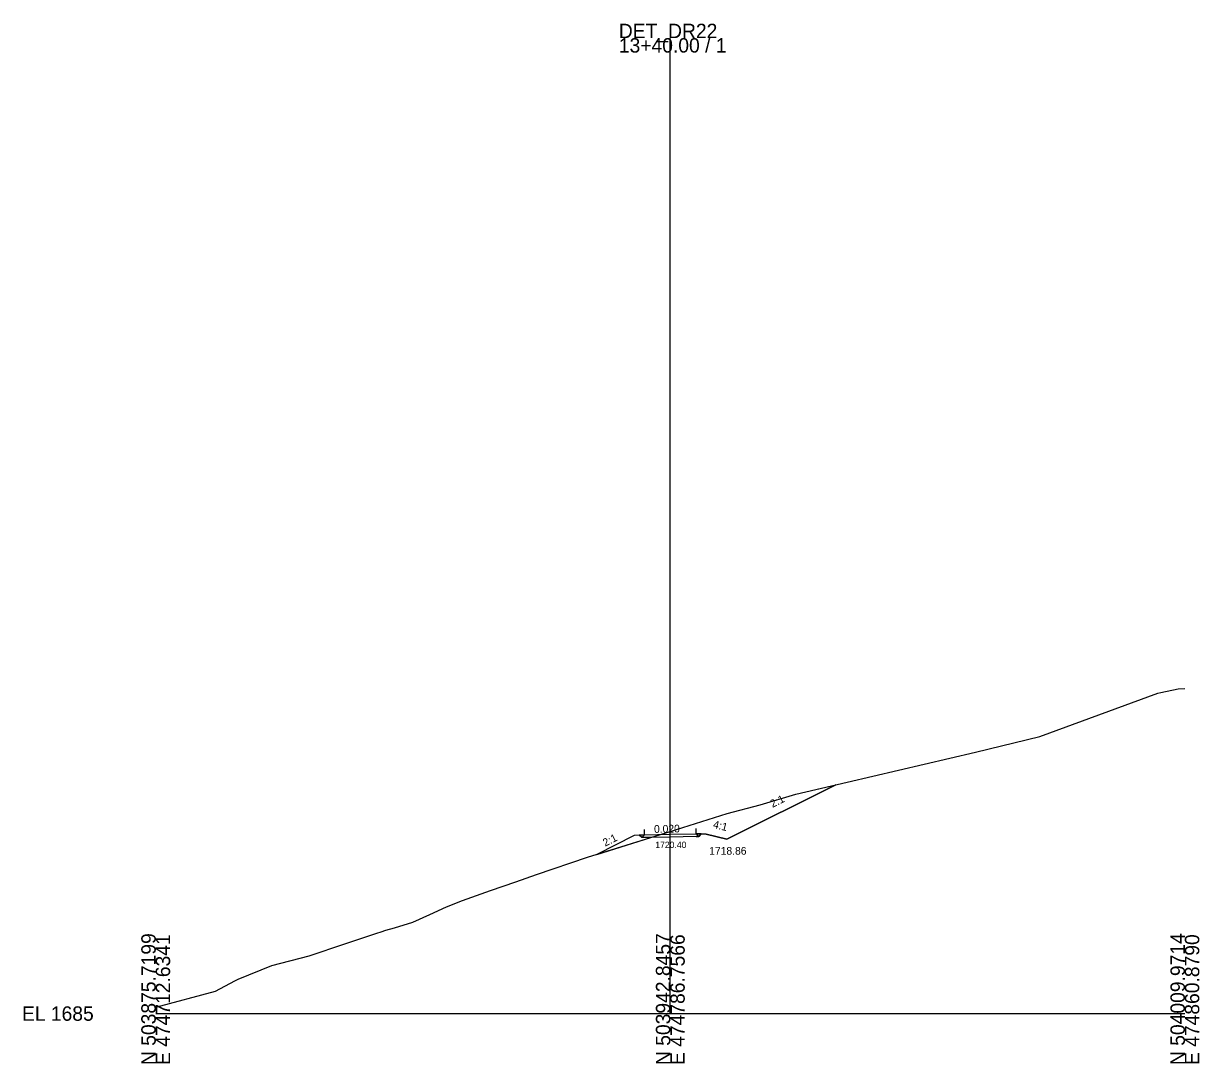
# Model space of a CAD drawing. Extents: x -26 to 1203, y -10 to 9633.
# Drawn here: x -25.7 to 202.8, y 8490.3 to 8692.3 of the extents above; entities that cross this region are included whole.
import ezdxf

# ---------------------------------------------------------------- set-up
doc = ezdxf.new("R2010")
doc.units = 0
for name, color, linetype in [('Exist Cross Section Cell', 7, 'Continuous'), ('Exist XS Center Line Elevation Label', 7, 'Continuous'), ('Exist XS Ground Line', 7, 'Continuous'), ('Prop XS Ditch Slope Text', 7, 'Continuous'), ('Prop XS Ditch Standard Text', 7, 'Continuous'), ('Prop XS Earthwork Shape', 7, 'Continuous'), ('Prop XS EOT Tick Mark', 7, 'Continuous'), ('Prop XS Finish Grade', 7, 'Continuous'), ('Prop XS Finish Grade Earthwork', 7, 'Continuous'), ('Prop XS Finish Grade Pavement', 7, 'Continuous'), ('Prop XS Pvmt Edge Slope', 7, 'Continuous'), ('Prop XS SE Text', 7, 'Continuous'), ('Prop XS Shoulder Borrow Shape', 7, 'Continuous'), ('Prop XS Side Slope Text', 7, 'Continuous'), ('Prop XS Subgrade Earthwork', 7, 'Continuous')]:
    doc.layers.add(name, color=color, linetype=linetype)

msp = doc.modelspace()

# ---------------------------------------------------------------- linework, layer by layer
at = {"layer": 'Exist Cross Section Cell'}
for p, q in [((100, 8500), (100, 8689.48)), ((0, 8500), (100, 8500)), ((100, 8500), (200, 8500))]:
    msp.add_line(p, q, dxfattribs=at)
at = {"layer": 'Exist XS Ground Line'}
msp.add_lwpolyline([(0, 8501.22), (11.63, 8504.36), (15.35, 8506.37), (16.01, 8506.68), (22.57, 8509.37), (29.81, 8511.22), (36.73, 8513.52), (43, 8515.6), (43.81, 8515.87), (44.71, 8516.17), (46.4, 8516.63), (49.95, 8517.77), (53.25, 8519.22), (56.49, 8520.73), (59.61, 8521.95), (65.05, 8523.88), (69.98, 8525.61), (74, 8527.01), (83.9, 8530.37), (100, 8535.4), (111.04, 8538.85), (117.49, 8540.54), (124.4, 8542.63), (159.31, 8550.8), (171.8, 8553.85), (194.74, 8562.27), (195.34, 8562.38), (198.67, 8563.07), (200, 8563.16)], dxfattribs=at)
at = {"layer": 'Prop XS Earthwork Shape'}
for points in [[(100, 8535.4), (111.04, 8538.85), (117.49, 8540.54), (124.4, 8542.63), (132.18, 8544.45), (111, 8533.86), (107, 8534.86), (106.02, 8534.9), (105.53, 8534.41), (105, 8534.4), (100, 8534.3), (96.24, 8534.22)], [(85.7, 8530.93), (96.24, 8534.22), (95, 8534.2), (94.45, 8534.19), (93.98, 8534.66), (93, 8534.58)]]:
    msp.add_lwpolyline(points, close=True, dxfattribs=at)
at = {"layer": 'Prop XS EOT Tick Mark'}
for p, q in [((95, 8534.74), (95, 8535.74)), ((105, 8534.94), (105, 8535.94))]:
    msp.add_line(p, q, dxfattribs=at)
at = {"layer": 'Prop XS Finish Grade'}
for p, q in [((95, 8534.74), (93.98, 8534.66)), ((105, 8534.94), (106.02, 8534.9))]:
    msp.add_line(p, q, dxfattribs=at)
at = {"layer": 'Prop XS Finish Grade Earthwork'}
for p, q in [((111, 8533.86), (132.18, 8544.45)), ((93, 8534.58), (85.7, 8530.93)), ((93.98, 8534.66), (93, 8534.58)), ((106.02, 8534.9), (107, 8534.86)), ((107, 8534.86), (111, 8533.86))]:
    msp.add_line(p, q, dxfattribs=at)
at = {"layer": 'Prop XS Finish Grade Pavement'}
for p, q in [((95, 8534.74), (100, 8534.84)), ((100, 8534.84), (105, 8534.94))]:
    msp.add_line(p, q, dxfattribs=at)
at = {"layer": 'Prop XS Pvmt Edge Slope'}
for p, q in [((95, 8534.74), (94.45, 8534.19)), ((105, 8534.94), (105.53, 8534.41))]:
    msp.add_line(p, q, dxfattribs=at)
at = {"layer": 'Prop XS Shoulder Borrow Shape'}
for points in [[(95, 8534.74), (94.45, 8534.19), (93.98, 8534.66)], [(105.53, 8534.41), (106.02, 8534.9), (105, 8534.94)]]:
    msp.add_lwpolyline(points, close=True, dxfattribs=at)
at = {"layer": 'Prop XS Subgrade Earthwork'}
for p, q in [((94.45, 8534.19), (93.98, 8534.66)), ((95, 8534.2), (94.45, 8534.19)), ((100, 8534.3), (95, 8534.2)), ((105, 8534.4), (100, 8534.3)), ((105, 8534.4), (105.53, 8534.41)), ((105.53, 8534.41), (106.02, 8534.9))]:
    msp.add_line(p, q, dxfattribs=at)

# ---------------------------------------------------------------- texts
at = {"layer": 'Exist Cross Section Cell'}
for s, p in [('DET_DR22', (90, 8689.48)), ('13+40.00 / 1', (90, 8686.68)), ('EL 1685', (-26, 8498.6))]:
    msp.add_text(s, height=2.8, dxfattribs=at).set_placement(p)
for s, p in [('N 503875.7199', (0, 8490)), ('E 474712.6341', (2.8, 8490)), ('N 503942.8457', (100, 8490)), ('E 474786.7566', (102.8, 8490)), ('N 504009.9714', (200, 8490)), ('E 474860.8790', (202.8, 8490))]:
    msp.add_text(s, height=2.8, rotation=90, dxfattribs=at).set_placement(p)
at = {"layer": 'Exist XS Center Line Elevation Label'}
msp.add_text('1720.40', height=1.25, dxfattribs=at).set_placement((97.09, 8532.15))
at = {"layer": 'Prop XS Ditch Slope Text'}
msp.add_text('4:1', height=1.5, rotation=345.9638, dxfattribs=at).set_placement((108.21, 8536.1))
at = {"layer": 'Prop XS Ditch Standard Text'}
msp.add_text('1718.86', height=1.5, dxfattribs=at).set_placement((107.56, 8530.86))
at = {"layer": 'Prop XS SE Text'}
msp.add_text('0.020', height=1.5, rotation=1.1458, dxfattribs=at).set_placement((96.85, 8535.1))
at = {"layer": 'Prop XS Side Slope Text'}
for p in [(119.86, 8539.96), (87.34, 8532.41)]:
    msp.add_text('2:1', height=1.5, rotation=26.5651, dxfattribs=at).set_placement(p)

doc.saveas('drawing.dxf')
